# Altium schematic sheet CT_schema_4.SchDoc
size 218 x 258 mm
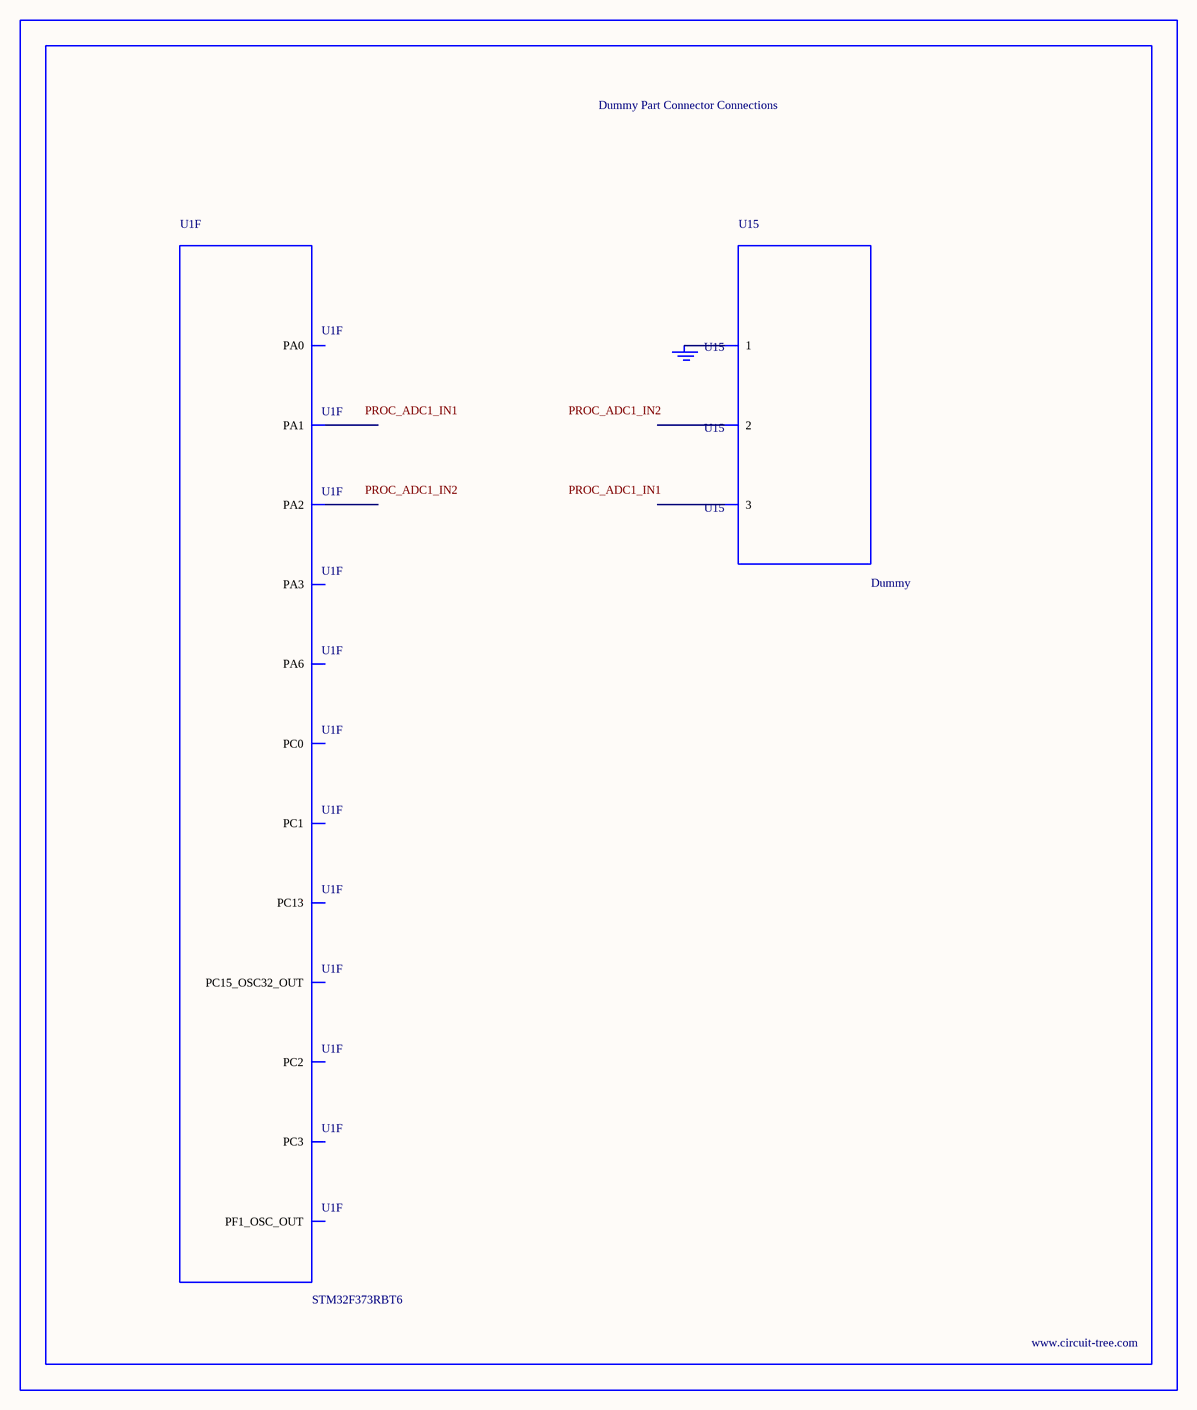
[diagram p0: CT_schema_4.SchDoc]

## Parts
BORDER3  (no value)
GND_INSTANCE_3_0  (no value)
U1  STM32F373RBT6  [LQFP64]  (part F of 6)
U15  Dummy  [DUMMY_PACKAGE_145]

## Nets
NetGND_INSTANCE_3_0_0: GND_INSTANCE_3_0.0(GND) U15.1

Not connected (* = marked no-connect by the designer): U1 2(PC13) 4(PC15_OSC32_OUT) 6(PF1_OSC_OUT) 8(PC0) 9(PC1) 10(PC2) 11(PC3) 14(PA0) 15(PA1) 16(PA2) 18(PA3) 22(PA6); U15 2 3

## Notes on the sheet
- Labels drawn without touching a wire or pin: PROC_ADC1_IN1, PROC_ADC1_IN2

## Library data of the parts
BORDER3 = BORDER_PAGE3
GND_INSTANCE_3_0 = GND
